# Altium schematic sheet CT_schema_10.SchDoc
size 274 x 160 mm
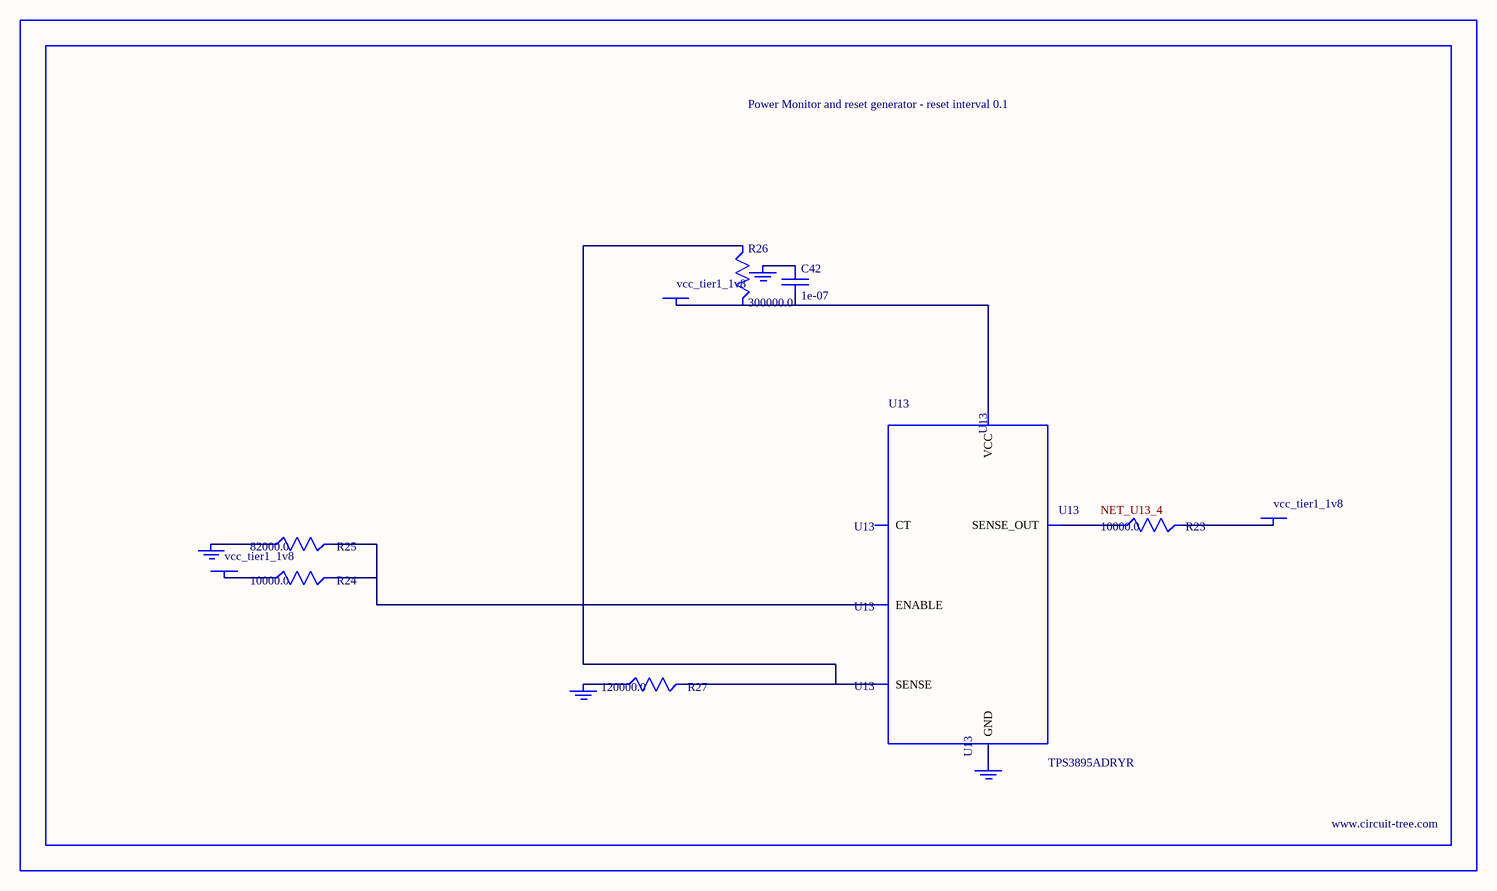
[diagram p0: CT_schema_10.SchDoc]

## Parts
BORDER9  (no value)
C42  1e-07  [C0402]
GND_INSTANCE_9_0  (no value)
GND_INSTANCE_9_1  (no value)
GND_INSTANCE_9_2  (no value)
GND_INSTANCE_9_3  (no value)
POWER_INSTANCE_9_0  vcc_tier1_1v8
POWER_INSTANCE_9_1  vcc_tier1_1v8
POWER_INSTANCE_9_2  vcc_tier1_1v8
R23  10000.0  [R0603]
R24  10000.0  [R0603]
R25  82000.0  [R0603]
R26  300000.0  [R0603]
R27  120000.0  [R0603]
U13  TPS3895ADRYR  [SON-6]

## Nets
NetC42_1: C42.1 GND_INSTANCE_9_2.0(GND)
NetC42_2: C42.2 POWER_INSTANCE_9_2.0(PWR) R26.2 U13.6(VCC)
NetGND_INSTANCE_9_0_0: GND_INSTANCE_9_0.0(GND) R25.1
NetGND_INSTANCE_9_1_0: GND_INSTANCE_9_1.0(GND) R27.1
NetGND_INSTANCE_9_3_0: GND_INSTANCE_9_3.0(GND) U13.2(GND)
NetPOWER_INSTANCE_9_0_0: POWER_INSTANCE_9_0.0(PWR) R24.1
NetPOWER_INSTANCE_9_1_0: POWER_INSTANCE_9_1.0(PWR) R23.2
NetR23_1: R23.1 U13.4(SENSE_OUT)
NetR24_2: R24.2 R25.2 U13.1(ENABLE)
NetR26_1: R26.1 R27.2 U13.3(SENSE)

Not connected (* = marked no-connect by the designer): U13 5(CT)

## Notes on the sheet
- Labels drawn without touching a wire or pin: NET_U13_4

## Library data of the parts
BORDER9 = BORDER_PAGE9
C42 = C0402C104K3RACTU
GND_INSTANCE_9_0-GND_INSTANCE_9_3 = GND
POWER_INSTANCE_9_0-POWER_INSTANCE_9_2 = PWR
R23 R24 = RC0603JR-0710KL
R25 = RC0603JR-0782KL
R26 = RC0603JR-07300KL
R27 = RC0603JR-07120KL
